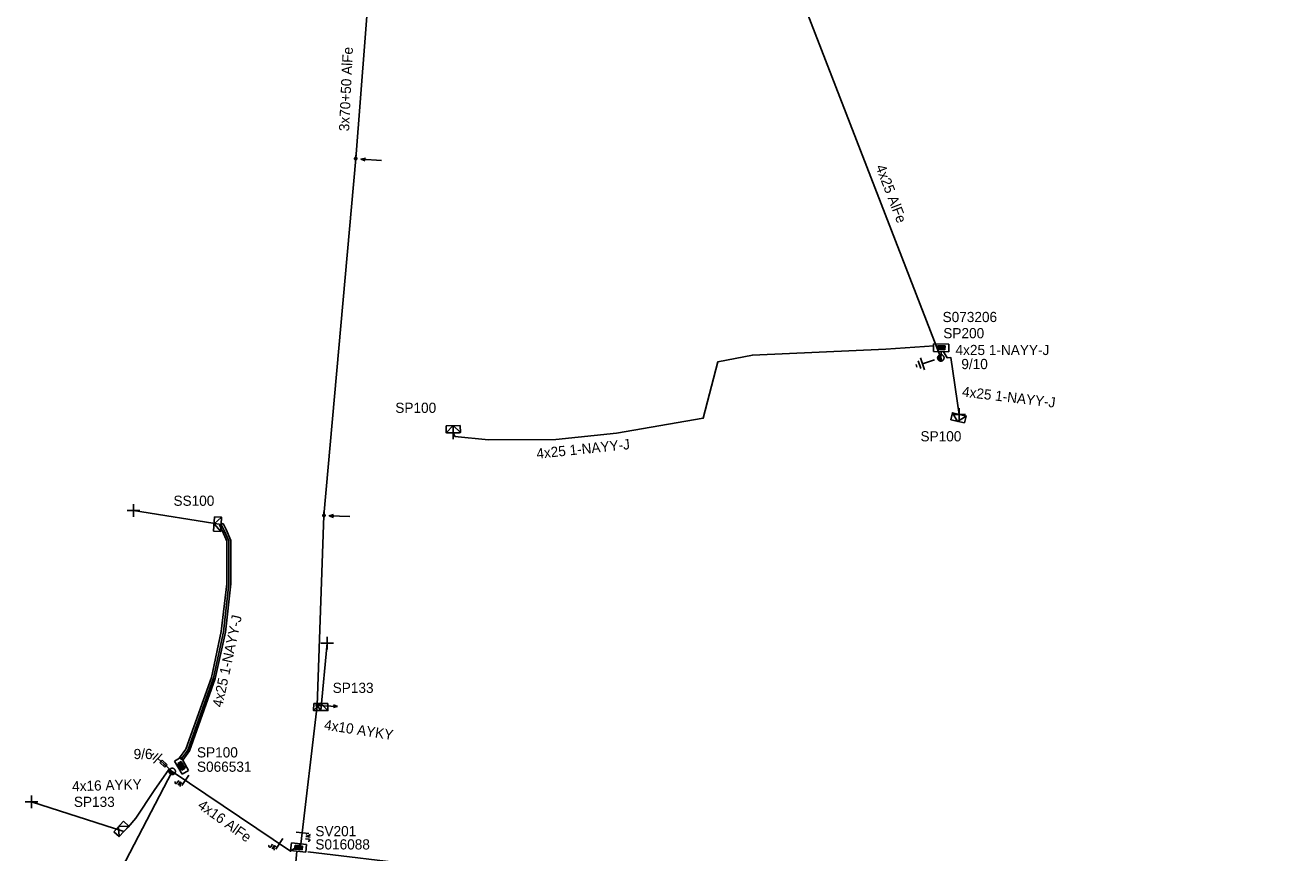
# Model space of a CAD drawing. Extents: x -717562 to -713845, y -1151196 to -1143903.
# Drawn here: x -717003.6 to -716879.6, y -1145066.7 to -1144985.4 of the extents above; entities that cross this region are included whole.
import ezdxf

# ---------------------------------------------------------------- set-up
doc = ezdxf.new("R2010")
doc.units = 0
for name, color, linetype in [('Vrstva 1', 7, 'Continuous'), ('Vrstva 12', 7, 'Continuous'), ('Vrstva 13', 7, 'Continuous'), ('Vrstva 14', 7, 'Continuous'), ('Vrstva 15', 7, 'Continuous'), ('Vrstva 16', 7, 'Continuous'), ('Vrstva 18', 7, 'Continuous'), ('Vrstva 2', 7, 'Continuous'), ('Vrstva 20', 7, 'Continuous'), ('Vrstva 28', 7, 'Continuous'), ('Vrstva 29', 7, 'Continuous'), ('Vrstva 30', 7, 'Continuous'), ('Vrstva 31', 7, 'Continuous'), ('Vrstva 33', 7, 'Continuous'), ('Vrstva 34', 7, 'Continuous'), ('Vrstva 5', 7, 'Continuous'), ('Vrstva 52', 7, 'Continuous'), ('Vrstva 54', 7, 'Continuous'), ('Vrstva 59', 7, 'Continuous'), ('Vrstva 6', 7, 'Continuous'), ('Vrstva 8', 7, 'Continuous'), ('Vrstva 9', 7, 'Continuous')]:
    doc.layers.add(name, color=color, linetype=linetype)

# ---------------------------------------------------------------- blocks, each defined once
blk = doc.blocks.new('NN440')
at = {"layer": 'Vrstva 2'}
for points in [[(0.63, 0), (0.63, 0.06), (0.62, 0.13), (0.6, 0.19), (0.58, 0.25), (0.55, 0.31), (0.51, 0.37), (0.47, 0.42), (0.42, 0.46), (0.37, 0.51), (0.32, 0.54), (0.26, 0.57), (0.2, 0.59), (0.13, 0.61), (0.07, 0.62), (0, 0.63), (-0.06, 0.62), (-0.13, 0.61), (-0.19, 0.59), (-0.26, 0.57), (-0.31, 0.54), (-0.37, 0.51), (-0.42, 0.46), (-0.47, 0.42), (-0.51, 0.37), (-0.54, 0.31), (-0.57, 0.25), (-0.6, 0.19), (-0.62, 0.13), (-0.63, 0.06), (-0.63, 0), (-0.63, -0.07), (-0.62, -0.14), (-0.6, -0.2), (-0.57, -0.26), (-0.54, -0.32), (-0.51, -0.37), (-0.47, -0.43), (-0.42, -0.47), (-0.37, -0.51), (-0.31, -0.55), (-0.26, -0.58), (-0.19, -0.6), (-0.13, -0.62), (-0.06, -0.63), (0, -0.63), (0.07, -0.63), (0.13, -0.62), (0.2, -0.6), (0.26, -0.58), (0.32, -0.55), (0.37, -0.51), (0.42, -0.47), (0.47, -0.43), (0.51, -0.37), (0.55, -0.32), (0.58, -0.26), (0.6, -0.2), (0.62, -0.14), (0.63, -0.07), (0.63, 0)], [(-0.63, 0), (0.63, 0)], [(-0.6, -0.18), (0.57, -0.18)], [(-0.51, -0.32), (0.5, -0.32)], [(-0.37, -0.47), (0.35, -0.47)]]:
    blk.add_lwpolyline(points, dxfattribs=at)
blk = doc.blocks.new('NN560')
at = {"layer": 'Vrstva 2'}
for points in [[(2, 0), (1.59, 0.14)], [(0, 0), (2, 0)], [(2, 0), (1.59, -0.13)]]:
    blk.add_lwpolyline(points, dxfattribs=at)
blk = doc.blocks.new('NN840')
at = {"layer": 'Vrstva 15'}
for points in [[(0, 0.62), (0, -0.63)], [(-0.75, -0.71), (-0.75, -0.66)], [(-0.73, -0.76), (-0.75, -0.71)], [(-0.66, -0.8), (-0.73, -0.76)], [(-0.63, -0.8), (-0.66, -0.8)], [(-0.56, -0.76), (-0.63, -0.8)], [(-0.54, -0.71), (-0.56, -0.76)], [(-0.54, -0.38), (-0.54, -0.71)], [(-0.33, -0.38), (-0.33, -0.8)], [(-0.33, -0.64), (-0.13, -0.38)], [(-0.26, -0.56), (-0.09, -0.8)]]:
    blk.add_lwpolyline(points, dxfattribs=at)
blk = doc.blocks.new('NN565')
at = {"layer": 'Vrstva 2'}
for points in [[(0.01, 0.53), (0.01, 2.53)], [(0.16, 0.94), (0.01, 0.53), (-0.12, 0.94)]]:
    blk.add_lwpolyline(points, dxfattribs=at)
blk = doc.blocks.new('NN800')
at = {"layer": 'Vrstva 1'}
for points in [[(-0.44, 0.44), (0.44, -0.44)], [(-0.44, -0.44), (0.44, 0.44)]]:
    blk.add_lwpolyline(points, dxfattribs=at)
blk = doc.blocks.new('NN820')
at = {"layer": 'Vrstva 13'}
for points in [[(0, 0), (0, -1.05)], [(-0.16, -0.81), (0.16, -0.81)], [(-0.16, -1.47), (-0.16, -0.81)], [(0, -1.05), (-0.06, -0.93)], [(0, -1.05), (0.06, -0.93)], [(0.16, -0.81), (0.16, -1.47)], [(0.16, -1.47), (-0.16, -1.47)], [(0, -1.47), (0, -1.87)]]:
    blk.add_lwpolyline(points, dxfattribs=at)
blk = doc.blocks.new('NN620')
at = {"layer": 'Vrstva 8'}
for points in [[(0.75, 0), (-0.75, 0)], [(-0.75, 0), (-0.75, -0.75)], [(0.75, -0.75), (0.75, 0)], [(-0.75, -0.75), (0.75, -0.75)], [(0.37, -0.18), (-0.38, -0.18)], [(-0.38, -0.18), (-0.38, -0.56)], [(-0.38, -0.56), (0.37, -0.56)], [(0.32, -0.23), (-0.33, -0.23)], [(-0.33, -0.23), (-0.33, -0.51)], [(-0.33, -0.51), (0.32, -0.51)], [(0.27, -0.27), (-0.28, -0.27)], [(-0.28, -0.27), (-0.28, -0.46)], [(-0.28, -0.46), (0.27, -0.46)], [(0.23, -0.32), (-0.23, -0.32)], [(-0.23, -0.32), (-0.23, -0.42)], [(-0.23, -0.42), (0.23, -0.42)], [(-0.19, -0.37), (0.19, -0.37)], [(0.23, -0.42), (0.23, -0.32)], [(0.27, -0.46), (0.27, -0.27)], [(0.32, -0.51), (0.32, -0.23)], [(0.37, -0.56), (0.37, -0.18)]]:
    blk.add_lwpolyline(points, dxfattribs=at)
blk = doc.blocks.new('NN630')
at = {"layer": 'Vrstva 9'}
for points in [[(0, -0.7), (-0.7, 0)], [(-0.7, -0.7), (-0.7, 0), (0.7, 0), (0.7, -0.7)], [(-0.7, -0.7), (0.7, -0.7)], [(0, -0.7), (0.7, 0)]]:
    blk.add_lwpolyline(points, dxfattribs=at)
blk = doc.blocks.new('NN810')
at = {"layer": 'Vrstva 14'}
for points in [[(0, -0.64), (0, -1.89)], [(0.63, -1.89), (-0.62, -1.89)], [(0.39, -2.2), (-0.4, -2.2)], [(0, -2.52), (-0.12, -2.52)], [(0.14, -2.52), (0, -2.52)]]:
    blk.add_lwpolyline(points, dxfattribs=at)
blk = doc.blocks.new('NN500')
at = {"layer": 'Vrstva 2'}
for points in [[(0, -0.24), (0.02, -0.23), (0.05, -0.23), (0.07, -0.22), (0.09, -0.22), (0.12, -0.2), (0.14, -0.19), (0.16, -0.18), (0.17, -0.16), (0.19, -0.14), (0.2, -0.12), (0.21, -0.1), (0.22, -0.07), (0.23, -0.05), (0.23, -0.02), (0.23, 0), (0.23, 0.02), (0.23, 0.05), (0.22, 0.07), (0.21, 0.1), (0.2, 0.12), (0.19, 0.14), (0.17, 0.16), (0.16, 0.17), (0.14, 0.19), (0.12, 0.2), (0.09, 0.21), (0.07, 0.22), (0.05, 0.23), (0.02, 0.23), (0, 0.23), (-0.03, 0.23), (-0.05, 0.23), (-0.07, 0.22), (-0.1, 0.21), (-0.12, 0.2), (-0.14, 0.19), (-0.16, 0.17), (-0.18, 0.16), (-0.19, 0.14), (-0.2, 0.12), (-0.22, 0.1), (-0.22, 0.07), (-0.23, 0.05), (-0.23, 0.02), (-0.24, 0), (-0.23, -0.02), (-0.23, -0.05), (-0.22, -0.07), (-0.22, -0.1), (-0.2, -0.12), (-0.19, -0.14), (-0.18, -0.16), (-0.16, -0.18), (-0.14, -0.19), (-0.12, -0.2), (-0.1, -0.22), (-0.07, -0.22), (-0.05, -0.23), (-0.03, -0.23), (0, -0.24)], [(0, -0.24), (0.02, -0.23), (0.05, -0.23), (0.07, -0.22), (0.09, -0.22), (0.12, -0.2), (0.14, -0.19), (0.16, -0.18), (0.17, -0.16), (0.19, -0.14), (0.2, -0.12), (0.21, -0.1), (0.22, -0.07), (0.23, -0.05), (0.23, -0.02), (0.23, 0), (0.23, 0.02), (0.23, 0.05), (0.22, 0.07), (0.21, 0.1), (0.2, 0.12), (0.19, 0.14), (0.17, 0.16), (0.16, 0.17), (0.14, 0.19), (0.12, 0.2), (0.09, 0.21), (0.07, 0.22), (0.05, 0.23), (0.02, 0.23), (0, 0.23), (-0.03, 0.23), (-0.05, 0.23), (-0.07, 0.22), (-0.1, 0.21), (-0.12, 0.2), (-0.14, 0.19), (-0.16, 0.17), (-0.18, 0.16), (-0.19, 0.14), (-0.2, 0.12), (-0.22, 0.1), (-0.22, 0.07), (-0.23, 0.05), (-0.23, 0.02), (-0.24, 0), (-0.23, -0.02), (-0.23, -0.05), (-0.22, -0.07), (-0.22, -0.1), (-0.2, -0.12), (-0.19, -0.14), (-0.18, -0.16), (-0.16, -0.18), (-0.14, -0.19), (-0.12, -0.2), (-0.1, -0.22), (-0.07, -0.22), (-0.05, -0.23), (-0.03, -0.23), (0, -0.24)], [(0, -0.21), (0.02, -0.2), (0.04, -0.2), (0.06, -0.2), (0.08, -0.19), (0.1, -0.18), (0.12, -0.17), (0.14, -0.15), (0.15, -0.14), (0.16, -0.12), (0.18, -0.1), (0.19, -0.08), (0.19, -0.06), (0.2, -0.04), (0.2, -0.02), (0.2, 0), (0.2, 0.02), (0.2, 0.04), (0.19, 0.06), (0.19, 0.08), (0.18, 0.1), (0.16, 0.12), (0.15, 0.14), (0.14, 0.15), (0.12, 0.17), (0.1, 0.18), (0.08, 0.19), (0.06, 0.19), (0.04, 0.2), (0.02, 0.2), (0, 0.2), (-0.02, 0.2), (-0.04, 0.2), (-0.06, 0.19), (-0.08, 0.19), (-0.1, 0.18), (-0.12, 0.17), (-0.14, 0.15), (-0.15, 0.14), (-0.17, 0.12), (-0.18, 0.1), (-0.19, 0.08), (-0.2, 0.06), (-0.2, 0.04), (-0.21, 0.02), (-0.21, 0), (-0.21, -0.02), (-0.2, -0.04), (-0.2, -0.06), (-0.19, -0.08), (-0.18, -0.1), (-0.17, -0.12), (-0.15, -0.14), (-0.14, -0.15), (-0.12, -0.17), (-0.1, -0.18), (-0.08, -0.19), (-0.06, -0.2), (-0.04, -0.2), (-0.02, -0.2), (0, -0.21)], [(0, -0.18), (0.02, -0.18), (0.04, -0.17), (0.05, -0.17), (0.07, -0.16), (0.09, -0.15), (0.1, -0.14), (0.12, -0.13), (0.13, -0.12), (0.14, -0.1), (0.15, -0.09), (0.16, -0.07), (0.17, -0.05), (0.17, -0.04), (0.17, -0.02), (0.17, 0), (0.17, 0.02), (0.17, 0.04), (0.17, 0.05), (0.16, 0.07), (0.15, 0.09), (0.14, 0.1), (0.13, 0.12), (0.12, 0.13), (0.1, 0.14), (0.09, 0.15), (0.07, 0.16), (0.05, 0.17), (0.04, 0.17), (0.02, 0.17), (0, 0.18), (-0.02, 0.17), (-0.04, 0.17), (-0.06, 0.17), (-0.07, 0.16), (-0.09, 0.15), (-0.1, 0.14), (-0.12, 0.13), (-0.13, 0.12), (-0.14, 0.1), (-0.15, 0.09), (-0.16, 0.07), (-0.17, 0.05), (-0.17, 0.04), (-0.18, 0.02), (-0.18, 0), (-0.18, -0.02), (-0.17, -0.04), (-0.17, -0.05), (-0.16, -0.07), (-0.15, -0.09), (-0.14, -0.1), (-0.13, -0.12), (-0.12, -0.13), (-0.1, -0.14), (-0.09, -0.15), (-0.07, -0.16), (-0.06, -0.17), (-0.04, -0.17), (-0.02, -0.18), (0, -0.18)], [(0, -0.15), (0.01, -0.15), (0.03, -0.14), (0.04, -0.14), (0.06, -0.13), (0.07, -0.13), (0.08, -0.12), (0.1, -0.11), (0.11, -0.1), (0.12, -0.09), (0.13, -0.07), (0.13, -0.06), (0.14, -0.05), (0.14, -0.03), (0.14, -0.02), (0.14, 0), (0.14, 0.01), (0.14, 0.03), (0.14, 0.04), (0.13, 0.06), (0.13, 0.07), (0.12, 0.09), (0.11, 0.1), (0.1, 0.11), (0.08, 0.12), (0.07, 0.13), (0.06, 0.13), (0.04, 0.14), (0.03, 0.14), (0.01, 0.14), (0, 0.15), (-0.02, 0.14), (-0.03, 0.14), (-0.05, 0.14), (-0.06, 0.13), (-0.07, 0.13), (-0.09, 0.12), (-0.1, 0.11), (-0.11, 0.1), (-0.12, 0.09), (-0.13, 0.07), (-0.13, 0.06), (-0.14, 0.04), (-0.14, 0.03), (-0.15, 0.01), (-0.15, 0), (-0.15, -0.02), (-0.14, -0.03), (-0.14, -0.05), (-0.13, -0.06), (-0.13, -0.07), (-0.12, -0.09), (-0.11, -0.1), (-0.1, -0.11), (-0.09, -0.12), (-0.07, -0.13), (-0.06, -0.13), (-0.05, -0.14), (-0.03, -0.14), (-0.02, -0.15), (0, -0.15)], [(0, -0.12), (0.01, -0.12), (0.02, -0.11), (0.03, -0.11), (0.05, -0.11), (0.06, -0.1), (0.07, -0.09), (0.08, -0.09), (0.09, -0.08), (0.09, -0.07), (0.1, -0.06), (0.11, -0.05), (0.11, -0.04), (0.11, -0.02), (0.11, -0.01), (0.12, 0), (0.11, 0.01), (0.11, 0.02), (0.11, 0.04), (0.11, 0.05), (0.1, 0.06), (0.09, 0.07), (0.09, 0.08), (0.08, 0.09), (0.07, 0.09), (0.06, 0.1), (0.05, 0.11), (0.03, 0.11), (0.02, 0.11), (0.01, 0.12), (0, 0.12), (-0.01, 0.12), (-0.03, 0.11), (-0.04, 0.11), (-0.05, 0.11), (-0.06, 0.1), (-0.07, 0.09), (-0.08, 0.09), (-0.09, 0.08), (-0.1, 0.07), (-0.1, 0.06), (-0.11, 0.05), (-0.11, 0.04), (-0.12, 0.02), (-0.12, 0.01), (-0.12, 0), (-0.12, -0.01), (-0.12, -0.02), (-0.11, -0.04), (-0.11, -0.05), (-0.1, -0.06), (-0.1, -0.07), (-0.09, -0.08), (-0.08, -0.09), (-0.07, -0.09), (-0.06, -0.1), (-0.05, -0.11), (-0.04, -0.11), (-0.03, -0.11), (-0.01, -0.12), (0, -0.12)], [(0, -0.09), (0.01, -0.09), (0.02, -0.09), (0.03, -0.08), (0.03, -0.08), (0.04, -0.08), (0.05, -0.07), (0.06, -0.07), (0.06, -0.06), (0.07, -0.05), (0.07, -0.04), (0.08, -0.04), (0.08, -0.03), (0.08, -0.02), (0.09, -0.01), (0.09, 0), (0.09, 0.01), (0.08, 0.02), (0.08, 0.03), (0.08, 0.03), (0.07, 0.04), (0.07, 0.05), (0.06, 0.06), (0.06, 0.06), (0.05, 0.07), (0.04, 0.07), (0.03, 0.08), (0.03, 0.08), (0.02, 0.08), (0.01, 0.09), (0, 0.09), (-0.01, 0.09), (-0.02, 0.08), (-0.03, 0.08), (-0.04, 0.08), (-0.04, 0.07), (-0.05, 0.07), (-0.06, 0.06), (-0.07, 0.06), (-0.07, 0.05), (-0.08, 0.04), (-0.08, 0.03), (-0.08, 0.03), (-0.09, 0.02), (-0.09, 0.01), (-0.09, 0), (-0.09, -0.01), (-0.09, -0.02), (-0.08, -0.03), (-0.08, -0.04), (-0.08, -0.04), (-0.07, -0.05), (-0.07, -0.06), (-0.06, -0.07), (-0.05, -0.07), (-0.04, -0.08), (-0.04, -0.08), (-0.03, -0.08), (-0.02, -0.09), (-0.01, -0.09), (0, -0.09)], [(0, -0.06), (0, -0.06), (0.01, -0.06), (0.02, -0.05), (0.02, -0.05), (0.03, -0.05), (0.03, -0.05), (0.04, -0.04), (0.04, -0.04), (0.05, -0.03), (0.05, -0.03), (0.05, -0.02), (0.05, -0.02), (0.05, -0.01), (0.06, -0.01), (0.06, 0), (0.06, 0.01), (0.05, 0.01), (0.05, 0.02), (0.05, 0.02), (0.05, 0.03), (0.05, 0.03), (0.04, 0.04), (0.04, 0.04), (0.03, 0.05), (0.03, 0.05), (0.02, 0.05), (0.02, 0.05), (0.01, 0.06), (0, 0.06), (0, 0.06), (-0.01, 0.06), (-0.01, 0.06), (-0.02, 0.05), (-0.02, 0.05), (-0.03, 0.05), (-0.03, 0.05), (-0.04, 0.04), (-0.04, 0.04), (-0.05, 0.03), (-0.05, 0.03), (-0.05, 0.02), (-0.06, 0.02), (-0.06, 0.01), (-0.06, 0.01), (-0.06, 0), (-0.06, -0.01), (-0.06, -0.01), (-0.06, -0.02), (-0.05, -0.02), (-0.05, -0.03), (-0.05, -0.03), (-0.04, -0.04), (-0.04, -0.04), (-0.03, -0.05), (-0.03, -0.05), (-0.02, -0.05), (-0.02, -0.05), (-0.01, -0.06), (-0.01, -0.06), (0, -0.06)], [(0, -0.03), (0, -0.03), (0, -0.03), (0.01, -0.03), (0.01, -0.03), (0.01, -0.02), (0.02, -0.02), (0.02, -0.02), (0.02, -0.02), (0.02, -0.02), (0.02, -0.01), (0.02, -0.01), (0.03, -0.01), (0.03, -0.01), (0.03, 0), (0.03, 0), (0.03, 0), (0.03, 0.01), (0.03, 0.01), (0.02, 0.01), (0.02, 0.01), (0.02, 0.02), (0.02, 0.02), (0.02, 0.02), (0.02, 0.02), (0.01, 0.02), (0.01, 0.02), (0.01, 0.03), (0, 0.03), (0, 0.03), (0, 0.03), (0, 0.03), (-0.01, 0.03), (-0.01, 0.03), (-0.01, 0.02), (-0.02, 0.02), (-0.02, 0.02), (-0.02, 0.02), (-0.02, 0.02), (-0.02, 0.02), (-0.03, 0.01), (-0.03, 0.01), (-0.03, 0.01), (-0.03, 0.01), (-0.03, 0), (-0.03, 0), (-0.03, 0), (-0.03, -0.01), (-0.03, -0.01), (-0.03, -0.01), (-0.03, -0.01), (-0.02, -0.02), (-0.02, -0.02), (-0.02, -0.02), (-0.02, -0.02), (-0.02, -0.02), (-0.01, -0.03), (-0.01, -0.03), (-0.01, -0.03), (0, -0.03), (0, -0.03)], [(0.23, 0), (0.7, 0)]]:
    blk.add_lwpolyline(points, dxfattribs=at)

msp = doc.modelspace()

# ---------------------------------------------------------------- linework, layer by layer
at = {"layer": 'Vrstva 1'}
for points in [[(-716976.49, -1145065.91), (-716974.89, -1145052.28), (-716974.23, -1145033.61), (-716971.11, -1144998.55), (-716967.97, -1144957.87), (-716967.57, -1144932.78)], [(-716913.64, -1145018.13), (-716927.39, -1144982.6), (-716943.05, -1144947.6)], [(-716976.49, -1145065.91), (-716977.52, -1145066.6), (-716989.13, -1145058.75)], [(-716867.87, -1145092.44), (-716868.57, -1145091.59), (-716897.18, -1145077.53), (-716943.12, -1145070.58), (-716975.82, -1145066.66)]]:
    msp.add_lwpolyline(points, dxfattribs=at)
at = {"layer": 'Vrstva 20'}
msp.add_lwpolyline([(-716984.14, -1145034.39), (-716983.84, -1145034.98), (-716983.37, -1145036.06), (-716983.37, -1145040.34), (-716983.91, -1145045.06), (-716984.9, -1145049.62), (-716987.43, -1145056.74), (-716988.09, -1145057.66), (-716988.42, -1145057.42), (-716987.79, -1145056.56), (-716985.28, -1145049.52), (-716984.31, -1145045), (-716983.77, -1145040.32), (-716983.77, -1145036.14), (-716984.2, -1145035.16), (-716984.5, -1145034.57)], close=True, dxfattribs=at)
at = {"layer": 'Vrstva 5'}
for points in [[(-716913.64, -1145018.13), (-716913.62, -1145017.51)], [(-716988.26, -1145057.54), (-716987.61, -1145056.65), (-716985.09, -1145049.57), (-716984.11, -1145045.03), (-716983.57, -1145040.33), (-716983.57, -1145036.1), (-716984.02, -1145035.07), (-716984.32, -1145034.48)], [(-716976.88, -1145066.59), (-716977.09, -1145068.78)]]:
    msp.add_lwpolyline(points, dxfattribs=at)
at = {"layer": 'Vrstva 52'}
for points in [[(-716914.31, -1145016.96), (-716919.05, -1145017.28), (-716932.14, -1145017.85), (-716935.54, -1145018.5), (-716936.97, -1145024.06), (-716945.51, -1145025.53), (-716951.47, -1145026.15), (-716958.06, -1145026.19), (-716961.36, -1145025.85), (-716961.53, -1145025.48)], [(-716913.42, -1145017.48), (-716913.03, -1145018.11), (-716912.66, -1145018.1), (-716911.83, -1145023.68)], [(-716974.89, -1145052.28), (-716974.54, -1145052.78)], [(-716989.13, -1145058.75), (-717000.75, -1145081.11)], [(-716989.13, -1145058.75), (-716989.47, -1145058.57), (-716990.92, -1145060.62), (-716992.71, -1145063.33), (-716993.45, -1145064.22), (-716993.88, -1145064.64)]]:
    msp.add_lwpolyline(points, dxfattribs=at)
at = {"layer": 'Vrstva 59'}
for points in [[(-716984.32, -1145034.48), (-716992.92, -1145033.13)], [(-716974.54, -1145052.78), (-716973.92, -1145046.14)], [(-716993.88, -1145064.64), (-717002.94, -1145061.75)]]:
    msp.add_lwpolyline(points, dxfattribs=at)

# ---------------------------------------------------------------- block references
at = {"layer": 'Vrstva 13', "xscale": 0.5}
for name, p, yscale, rotation in [('NN500', (-716971.11, -1144998.55), 0.5, 90), ('NN440', (-716913.64, -1145018.13), 0.49999999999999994, -72.3623583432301), ('NN500', (-716974.23, -1145033.61), 0.5, 90), ('NN500', (-716974.89, -1145052.28), 0.5, 90), ('NN440', (-716989.13, -1145058.75), 0.5000000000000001, -42.23976116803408)]:
    msp.add_blockref(name, p, dxfattribs=dict(at, yscale=yscale, rotation=rotation))
at = {"layer": 'Vrstva 13'}
for name, p, rotation in [('NN565', (-716971.11, -1144998.55), -93.89832502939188), ('NN565', (-716974.23, -1145033.61), -91.70455000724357), ('NN560', (-716974.89, -1145052.28), -2.356335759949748)]:
    msp.add_blockref(name, p, dxfattribs=dict(at, rotation=rotation))
at = {"layer": 'Vrstva 15'}
for p, rotation in [((-716913.64, -1145018.13), -72.36235830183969), ((-716989.13, -1145058.75), -131.8947237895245)]:
    msp.add_blockref('NN810', p, dxfattribs=dict(at, rotation=rotation))
at = {"layer": 'Vrstva 16', "rotation": -131.8947237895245}
msp.add_blockref('NN820', (-716989.13, -1145058.75), dxfattribs=at)
at = {"layer": 'Vrstva 18'}
for p, rotation in [((-716987.83, -1145059.63), -34.07974615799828), ((-716978.61, -1145065.87), -33.92644344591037), ((-716976.35, -1145064.79), 83.93737219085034)]:
    msp.add_blockref('NN840', p, dxfattribs=dict(at, rotation=rotation))
at = {"layer": 'Vrstva 28'}
for p, rotation in [((-716913.62, -1145017.51), 178.48600719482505), ((-716988.54, -1145058.39), 119.99999996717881), ((-716976.76, -1145066.6), 173.93699999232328)]:
    msp.add_blockref('NN620', p, dxfattribs=dict(at, rotation=rotation))
at = {"layer": 'Vrstva 31'}
for p, rotation in [((-716911.83, -1145023.68), -13.166436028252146), ((-716961.53, -1145025.48), -179.32429721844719), ((-716984.32, -1145034.48), -93.57633437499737), ((-716974.54, -1145052.78), 179.63741111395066), ((-716993.88, -1145064.64), -132.85032507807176)]:
    msp.add_blockref('NN630', p, dxfattribs=dict(at, rotation=rotation))
at = {"layer": 'Vrstva 34'}
for p, rotation in [((-716911.83, -1145023.68), 44.99999995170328), ((-716961.53, -1145025.48), 45), ((-716992.92, -1145033.13), 45), ((-716973.92, -1145046.14), 45), ((-717002.94, -1145061.75), 44.99999995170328)]:
    msp.add_blockref('NN800', p, dxfattribs=dict(at, rotation=rotation))

# ---------------------------------------------------------------- texts
at = {"layer": 'Vrstva 12'}
for s, p in [('9/10', (-716911.63, -1145019.23)), ('9/6', (-716992.92, -1145057.54))]:
    msp.add_text(s, height=1, dxfattribs=at).set_placement(p)
at = {"layer": 'Vrstva 2'}
for s, rotation, p in [('3x70+50 AlFe', 87.335, (-716971.76, -1144995.88)), ('4x25 AlFe', 290.997, (-716920.06, -1144999.36)), ('4x16 AlFe', 324.449, (-716986.71, -1145062.27))]:
    msp.add_text(s, height=1, rotation=rotation, dxfattribs=at).set_placement(p)
at = {"layer": 'Vrstva 29'}
for s, p in [('S073206', (-716913.47, -1145014.61)), ('S066531', (-716986.7, -1145058.79)), ('S016088', (-716975.07, -1145066.42))]:
    msp.add_text(s, height=1, dxfattribs=at).set_placement(p)
at = {"layer": 'Vrstva 30'}
for s, p in [('SP200', (-716913.4, -1145016.2)), ('SP100', (-716986.7, -1145057.38)), ('SV201', (-716975.07, -1145065.12))]:
    msp.add_text(s, height=1, dxfattribs=at).set_placement(p)
at = {"layer": 'Vrstva 33'}
for s, p in [('SP100', (-716967.22, -1145023.53)), ('SP100', (-716915.64, -1145026.33)), ('SS100', (-716989.01, -1145032.66)), ('SP133', (-716973.37, -1145051.04)), ('SP133', (-716998.79, -1145062.24))]:
    msp.add_text(s, height=1, dxfattribs=at).set_placement(p)
at = {"layer": 'Vrstva 54'}
for s, rotation, p in [('4x25 1-NAYY-J', 353.12, (-716911.6, -1145021.92)), ('4x25 1-NAYY-J', 5.946, (-716953.31, -1145028.04)), ('4x10 AYKY', 351.263, (-716974.26, -1145054.64)), ('4x16 AYKY', 1.758, (-716998.95, -1145060.71))]:
    msp.add_text(s, height=1, rotation=rotation, dxfattribs=at).set_placement(p)
at = {"layer": 'Vrstva 6'}
msp.add_text('4x25 1-NAYY-J', height=1, dxfattribs=at).set_placement((-716912.2, -1145017.85))
msp.add_text('4x25 1-NAYY-J', height=1, rotation=77.819, dxfattribs=at).set_placement((-716984.22, -1145052.52))

doc.saveas('drawing.dxf')
